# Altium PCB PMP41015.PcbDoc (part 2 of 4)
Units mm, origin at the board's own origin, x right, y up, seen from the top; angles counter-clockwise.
Board outline 173 x 85 mm, 2 copper layers (Top Layer, Bottom Layer), stack 1.575 mm thick; 89 components, 48 nets, 216 pads, 3458 vias.
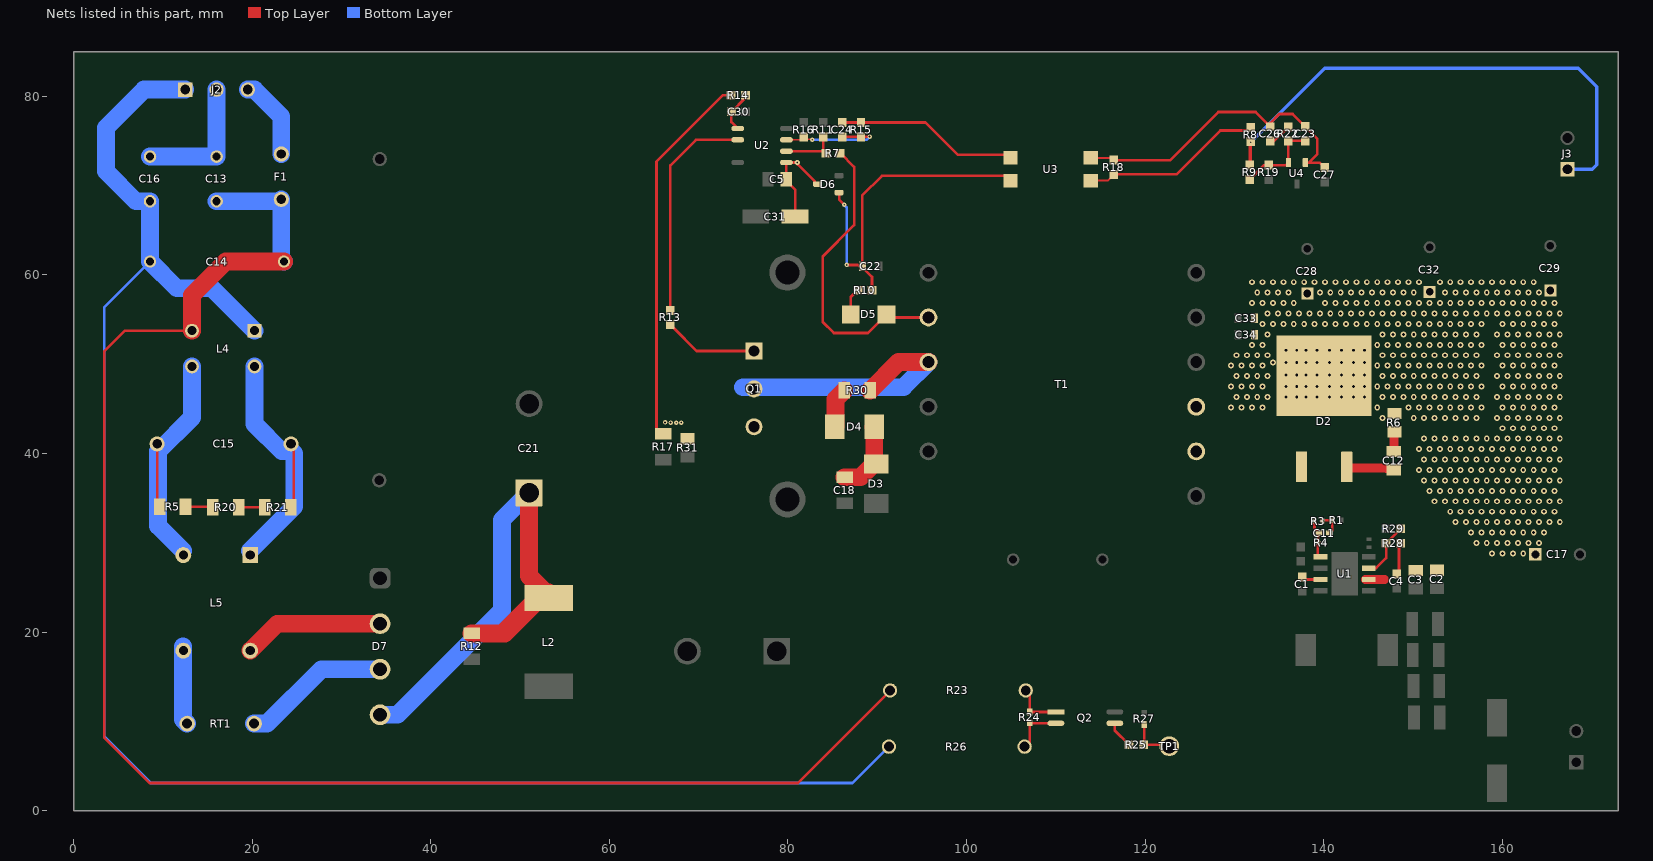
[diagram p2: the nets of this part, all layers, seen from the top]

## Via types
v1: diameter 0.4, hole 0.2, Top Layer to Bottom Layer, 2240 vias
v2: diameter 0.66, hole 0.33, Top Layer to Bottom Layer, 1066 vias
v3: diameter 0.5, hole 0.2, Top Layer to Bottom Layer, 105 vias
v4: diameter 0.67, hole 0.33, Top Layer to Bottom Layer, tented both sides, 41 vias
v5: diameter 0.5, hole 0.2, Top Layer to Bottom Layer, tented both sides, 4 vias
v6: diameter 0.61, hole 0.203, Top Layer to Bottom Layer, tented both sides, 2 vias

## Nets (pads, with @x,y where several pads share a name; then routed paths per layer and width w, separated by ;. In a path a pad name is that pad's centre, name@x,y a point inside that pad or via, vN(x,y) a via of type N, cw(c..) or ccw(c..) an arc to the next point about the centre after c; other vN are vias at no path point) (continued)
+24V: C2.1 C3.1 C4.1 C17.1 C28.1 C29.1 C32.1 C33.2 C34.2 D2.4 J3.1 R6.2 R8.2 R9.2 R28.2 U1.2 | length 63.7
  Top Layer w0.3: C4.1@148.178,26.505 148.438,26.764 148.438,29.759 R28.2@148.597,29.919
  Top Layer w0.4: R9.2@131.724,72.288 131.775,72.339 131.775,74.801 v6(131.826,74.851)
  Top Layer w1: U1.2@144.659,25.883 U1.2@145.048,25.883 146.841,25.883
  Bottom Layer w0.4: v6(131.826,74.851) 140.134,83.16 168.504,83.16 170.586,81.077 170.586,72.345 170.086,71.844 J3.1@167.307,71.844
  other v2: 158.852,28.804 160.02,28.804 161.188,28.804 162.357,28.804 157.099,29.972 158.267,29.972 159.436,29.972 160.604,29.972 161.773,29.972 162.941,29.972 164.109,29.972 156.515,31.14 157.683,31.14 158.852,31.14 160.02,31.14 161.188,31.14 162.357,31.14 163.525,31.14 164.694,31.14 154.762,32.309 155.931,32.309 157.099,32.309 158.267,32.309 159.436,32.309 160.604,32.309 161.773,32.309 162.941,32.309 164.109,32.309 165.278,32.309 166.446,32.309 154.178,33.477 155.346,33.477 156.515,33.477 157.683,33.477 158.852,33.477 160.02,33.477 161.188,33.477 162.357,33.477 163.525,33.477 164.694,33.477 165.862,33.477 152.425,34.646 153.594,34.646 154.762,34.646 155.931,34.646 157.099,34.646 158.267,34.646 159.436,34.646 160.604,34.646 161.773,34.646 162.941,34.646 164.109,34.646 165.278,34.646 166.446,34.646 151.841,35.814 153.01,35.814 154.178,35.814 155.346,35.814 156.515,35.814 157.683,35.814 158.852,35.814 160.02,35.814 161.188,35.814 162.357,35.814 163.525,35.814 164.694,35.814 165.862,35.814 151.257,36.982 152.425,36.982 153.594,36.982 154.762,36.982 155.931,36.982 157.099,36.982 158.267,36.982 159.436,36.982 160.604,36.982 161.773,36.982 162.941,36.982 164.109,36.982 165.278,36.982 166.446,36.982 150.673,38.151 151.841,38.151 153.01,38.151 154.178,38.151 155.346,38.151 156.515,38.151 157.683,38.151 158.852,38.151 160.02,38.151 161.188,38.151 162.357,38.151 163.525,38.151 164.694,38.151 165.862,38.151 151.257,39.319 152.425,39.319 153.594,39.319 154.762,39.319 155.931,39.319 157.099,39.319 158.267,39.319 159.436,39.319 160.604,39.319 161.773,39.319 162.941,39.319 164.109,39.319 165.278,39.319 166.446,39.319 150.673,40.488 151.841,40.488 153.01,40.488 154.178,40.488 155.346,40.488 156.515,40.488 157.683,40.488 158.852,40.488 160.02,40.488 161.188,40.488 162.357,40.488 163.525,40.488 164.694,40.488 165.862,40.488 151.257,41.656 152.425,41.656 153.594,41.656 154.762,41.656 155.931,41.656 157.099,41.656 158.267,41.656 159.436,41.656 160.604,41.656 161.773,41.656 162.941,41.656 164.109,41.656 165.278,41.656 166.446,41.656 160.02,42.824 161.188,42.824 162.357,42.824 163.525,42.824 164.694,42.824 165.862,42.824 146.583,43.993 150.089,43.993 151.257,43.993 152.425,43.993 153.594,43.993 154.762,43.993 155.931,43.993 157.099,43.993 159.436,43.993 160.604,43.993 161.773,43.993 162.941,43.993 164.109,43.993 165.278,43.993 166.446,43.993 129.642,45.161 130.81,45.161 131.978,45.161 133.147,45.161 145.999,45.161 149.504,45.161 150.673,45.161 151.841,45.161 153.01,45.161 154.178,45.161 155.346,45.161 156.515,45.161 157.683,45.161 160.02,45.161 161.188,45.161 162.357,45.161 163.525,45.161 164.694,45.161 165.862,45.161 130.226,46.33 131.394,46.33 132.563,46.33 133.731,46.33 146.583,46.33 147.752,46.33 148.92,46.33 150.089,46.33 151.257,46.33 152.425,46.33 153.594,46.33 154.762,46.33 155.931,46.33 157.099,46.33 159.436,46.33 160.604,46.33 161.773,46.33 162.941,46.33 164.109,46.33 165.278,46.33 166.446,46.33 129.642,47.498 130.81,47.498 131.978,47.498 133.147,47.498 145.999,47.498 147.168,47.498 148.336,47.498 149.504,47.498 150.673,47.498 151.841,47.498 153.01,47.498 154.178,47.498 155.346,47.498 156.515,47.498 157.683,47.498 160.02,47.498 161.188,47.498 162.357,47.498 163.525,47.498 164.694,47.498 165.862,47.498 130.226,48.666 131.394,48.666 132.563,48.666 133.731,48.666 146.583,48.666 147.752,48.666 148.92,48.666 150.089,48.666 151.257,48.666 152.425,48.666 153.594,48.666 154.762,48.666 155.931,48.666 157.099,48.666 159.436,48.666 160.604,48.666 161.773,48.666 162.941,48.666 164.109,48.666 165.278,48.666 166.446,48.666 129.642,49.835 130.81,49.835 131.978,49.835 133.147,49.835 145.999,49.835 147.168,49.835 148.336,49.835 149.504,49.835 150.673,49.835 151.841,49.835 153.01,49.835 154.178,49.835 155.346,49.835 156.515,49.835 157.683,49.835 160.02,49.835 161.188,49.835 162.357,49.835 163.525,49.835 164.694,49.835 165.862,49.835 130.226,51.003 131.394,51.003 132.563,51.003 133.731,51.003 146.583,51.003 147.752,51.003 148.92,51.003 150.089,51.003 151.257,51.003 152.425,51.003 153.594,51.003 154.762,51.003 155.931,51.003 157.099,51.003 159.436,51.003 160.604,51.003 161.773,51.003 162.941,51.003 164.109,51.003 165.278,51.003 166.446,51.003 131.978,52.172 133.147,52.172 145.999,52.172 147.168,52.172 148.336,52.172 149.504,52.172 150.673,52.172 151.841,52.172 153.01,52.172 154.178,52.172 155.346,52.172 156.515,52.172 157.683,52.172 160.02,52.172 161.188,52.172 162.357,52.172 163.525,52.172 164.694,52.172 165.862,52.172 133.731,53.34 146.583,53.34 147.752,53.34 148.92,53.34 150.089,53.34 151.257,53.34 152.425,53.34 153.594,53.34 154.762,53.34 155.931,53.34 157.099,53.34 159.436,53.34 160.604,53.34 161.773,53.34 162.941,53.34 164.109,53.34 165.278,53.34 166.446,53.34 133.147,54.508 134.315,54.508 135.484,54.508 136.652,54.508 137.82,54.508 138.989,54.508 140.157,54.508 141.326,54.508 142.494,54.508 143.662,54.508 144.831,54.508 145.999,54.508 147.168,54.508 148.336,54.508 149.504,54.508 150.673,54.508 151.841,54.508 153.01,54.508 154.178,54.508 155.346,54.508 156.515,54.508 157.683,54.508 160.02,54.508 161.188,54.508 162.357,54.508 163.525,54.508 164.694,54.508 165.862,54.508 133.731,55.677 134.899,55.677 136.068,55.677 137.236,55.677 138.405,55.677 139.573,55.677 140.741,55.677 141.91,55.677 143.078,55.677 144.247,55.677 145.415,55.677 146.583,55.677 147.752,55.677 148.92,55.677 150.089,55.677 151.257,55.677 152.425,55.677 153.594,55.677 154.762,55.677 155.931,55.677 157.099,55.677 158.267,55.677 159.436,55.677 160.604,55.677 161.773,55.677 162.941,55.677 164.109,55.677 165.278,55.677 166.446,55.677 131.978,56.845 133.147,56.845 134.315,56.845 135.484,56.845 136.652,56.845 140.157,56.845 141.326,56.845 142.494,56.845 143.662,56.845 144.831,56.845 145.999,56.845 147.168,56.845 148.336,56.845 149.504,56.845 150.673,56.845 151.841,56.845 153.01,56.845 154.178,56.845 155.346,56.845 156.515,56.845 157.683,56.845 158.852,56.845 160.02,56.845 161.188,56.845 162.357,56.845 163.525,56.845 164.694,56.845 165.862,56.845 132.563,58.014 133.731,58.014 134.899,58.014 136.068,58.014 139.573,58.014 140.741,58.014 141.91,58.014 143.078,58.014 144.247,58.014 145.415,58.014 146.583,58.014 147.752,58.014 148.92,58.014 150.089,58.014 153.594,58.014 154.762,58.014 155.931,58.014 157.099,58.014 158.267,58.014 159.436,58.014 160.604,58.014 161.773,58.014 162.941,58.014 164.109,58.014 131.978,59.182 133.147,59.182 134.315,59.182 135.484,59.182 136.652,59.182 137.82,59.182 138.989,59.182 140.157,59.182 141.326,59.182 142.494,59.182 143.662,59.182 144.831,59.182 145.999,59.182 147.168,59.182 148.336,59.182 149.504,59.182 150.673,59.182 153.01,59.182 154.178,59.182 155.346,59.182 156.515,59.182 157.683,59.182 158.852,59.182 160.02,59.182 161.188,59.182 162.357,59.182 163.525,59.182
  other v4: 135.765,46.33 136.983,46.33 138.023,46.33 139.239,46.33 140.649,46.33 142.008,46.33 143.359,46.33 144.571,46.33 135.768,47.498 136.987,47.498 138.027,47.498 139.242,47.498 140.652,47.498 142.011,47.498 143.362,47.498 144.574,47.498 135.768,48.767 136.987,48.767 138.027,48.767 139.242,48.767 140.652,48.767 142.011,48.767 143.362,48.767 144.574,48.767 134.315,50.189 135.765,50.189 136.983,50.189 138.023,50.189 139.239,50.189 140.649,50.189 142.008,50.189 143.359,50.189 144.571,50.189 135.765,51.561 136.983,51.561 138.023,51.561 139.239,51.561 140.649,51.561 142.008,51.561 143.359,51.561 144.571,51.561
BOOT: C1.1 U1.7 | length 2.1
  Top Layer w0.2: C1.1@137.623,26.177 C1.1@137.918,25.883
  Top Layer w0.3: C1.1@137.918,25.883 U1.7@139.648,25.883
Earth: C13.2 C16.1 J2.2 | length 15
  Bottom Layer w2: C16.1@8.55,73.25 C13.2@16,73.25 J2.2@16,80.75
FB: C11.2 R3.1 R4.2 U1.5 | length 4.4
  Top Layer w0.2: 139.325,28.745 U1.5@139.648,28.423 ; R4.2@139.325,29.919 R4.2@139.394,29.987
  Top Layer w0.3: R3.1@138.971,32.436 138.971,31.592 C11.2@139.473,31.09 139.394,31.011 R4.2@139.394,29.987 ; 139.325,28.745 R4.2@139.325,29.919
L: F1.2 J2.3 | length 9.2
  Bottom Layer w2: J2.3@19.5,80.75 20.24,80.75 23.25,77.74 F1.2@23.25,73.54
N: C14.2 C16.2 J2.1 L4.1 R26.1 | length 190.6
  Bottom Layer w0.3: C14.2@8.55,61.5 3.404,56.354 3.404,8.331 8.636,3.099 87.224,3.099 R26.1@91.298,7.173
  Bottom Layer w2: J2.1@12.5,80.75 7.877,80.75 3.607,76.479 3.607,71.603 6.959,68.25 C16.2@8.55,68.25 C14.2@8.55,61.5 11.55,58.5 15.5,58.5 L4.1@20.25,53.75
NetC5_1: C5.1 C31.1 D6.3 U2.1 | length 11.3
  Top Layer w0.3: U2.1@79.78,72.544 U2.1@79.825,72.59 ; C31.1@80.803,66.541 80.803,69.547 79.79,70.56 C5.1@79.79,70.726 79.825,70.761 U2.1@79.825,72.59 ; D6.3@83.318,70.162 83.118,70.162 82.968,70.312 82.968,70.512 81.106,72.375 81.106,72.531 v6(81.046,72.59) U2.1@79.825,72.59
NetC11_1: C11.1 R1.1 R3.2 | length 2.7
  Top Layer w0.3: R3.2@139.871,32.436 139.947,32.512 R1.1@140.953,32.512 140.953,31.369 C11.1@140.673,31.09
NetC12_1: C12.1 D2.1 D2.3 T1.8 T1.9 | length 5.5
  Top Layer w1: D2.3@142.586,38.493 142.586,38.388 146.967,38.388 147.028,38.327 147.717,38.327 C12.1@147.852,38.192
NetC12_2: C12.2 R6.1 | length 2.2
  Top Layer w1: C12.2@147.852,40.224 147.889,40.261 147.889,42.404 R6.1@147.926,42.44
NetC13_1: C13.1 C14.1 F1.1 L4.4 R23.1 | length 178.8
  Top Layer w0.3: L4.4@13.25,53.75 5.744,53.75 3.404,51.41 3.404,8.179 8.484,3.099 81.13,3.099 91.435,13.404 R23.1@91.435,13.462
  Top Layer w2: L4.4@13.25,53.75 13.25,57.725 17.025,61.5 C14.1@23.55,61.5
  Bottom Layer w2: C13.1@16,68.25 23.04,68.25 F1.1@23.25,68.46 23.25,61.8 C14.1@23.55,61.5
NetC15_1: C15.1 L4.3 L5.2 R5.2 | length 30.5
  Top Layer w0.3: C15.1@9.34,41.072 9.34,34.32 R5.2@9.624,34.036
  Bottom Layer w2: L5.2@12.25,29.1 9.458,31.892 9.458,40.25 13.25,44.042 L4.3@13.25,49.75
NetC15_2: C15.2 L4.2 L5.1 R21.1 | length 32.6
  Top Layer w0.3: C15.2@24.34,41.072 24.649,40.763 R21.1@24.649,33.871
  Bottom Layer w1: C15.2@24.458,40.25 24.7,40.008
  Bottom Layer w2: L5.1@19.75,29.1 24.7,34.05 24.7,40.008 ; L4.2@20.25,49.75 20.25,43.301 23.301,40.25 C15.2@24.458,40.25
NetC18_2: C18.2 D3.1 D4.1 | length 8.7
  Top Layer w2: C18.2@86.335,37.34 88.127,37.34 89.599,38.811 D3.1@89.742,38.811 ; D4.1@89.583,42.977 D4.1@89.662,42.897 ; D4.1@89.662,42.977 D4.1@89.662,42.897 ; D3.1@89.742,38.891 D3.1@89.821,38.811 ; D4.1@89.742,42.818 D4.1@89.662,42.897 ; D3.1@89.891,38.811 D3.1@89.821,38.811 ; D4.1@89.662,42.897 89.662,38.891 D3.1@89.742,38.811 ; D3.1@89.742,38.811 D3.1@89.821,38.811
NetC21_1: C21.1 D7.4 L2.1 R12.1 | length 62.5
  Top Layer w2: R12.1@44.571,19.847 48.021,19.847 ; C21.1@51.003,35.585 51.003,26.284 L2.1@52.861,24.426 ; 48.021,19.847 48.283,19.847 L2.1@52.611,24.176 ; 48.021,19.847 52.35,24.176 L2.1@52.611,24.176 ; L2.1@52.611,24.176 52.961,24.176 53.211,24.426 L2.1@52.861,24.426 ; L2.1@52.611,24.176 L2.1@52.861,24.426
  Bottom Layer w2: D7.4@34.32,10.733 36.27,10.733 38.091,12.554 47.955,22.418 47.955,32.537 C21.1@51.003,35.585
NetC22_2: C22.2 D6.1 R10.1 U3.4 | length 39.3
  Top Layer w0.3: D6.1@85.718,69.212 85.755,69.176 85.755,68.408 v3(86.296,67.867) ; v3(86.589,61.112) 87.824,61.112 88.155,60.782 C22.2@88.316,60.943 ; C22.2@88.365,60.96 88.332,60.96 C22.2@88.316,60.943 ; R10.1@89.421,58.268 89.421,59.779 88.316,60.884 C22.2@88.316,60.943 ; U3.4@104.923,70.561 104.39,71.095 90.526,71.095 88.316,68.885 C22.2@88.316,60.943
  Bottom Layer w0.3: v3(86.296,67.867) 86.296,67.813 86.589,67.521 v3(86.589,61.112)
NetC23_1: C23.1 R9.1 R19.2 R22.2 U4.2 | length 9.4
  Top Layer w0.3: R9.1@131.724,70.688 133.324,72.288 R19.2@133.833,72.288 135.768,72.288 U4.2@136.058,72.578 136.043,72.593 R22.2@136.043,74.99 136.068,75.015 C23.1@137.922,75.015
NetC23_2: C23.2 C26.2 C27.1 R18.1 U3.2 U4.1 | length 35.8
  Top Layer w0.2: U3.2@113.923,73.101 116.268,73.101 R18.1@116.51,72.86
  Top Layer w0.3: R18.1@116.51,72.86 122.822,72.86 128.207,78.245 132.382,78.245 C26.2@134.036,76.591 134.036,77.026 135.026,78.016 136.521,78.016 C23.2@137.922,76.615 139.294,75.244 139.294,73.52 138.351,72.578 ; U4.1@137.958,72.578 138.351,72.578 ; C27.1@140.106,72.009 139.537,72.578 138.351,72.578
NetC24_1: C24.1 R15.2 R16.2 U2.3 | length 13.2
  Top Layer w0.2: U2.3@79.825,75.13 81.674,75.13 R16.2@81.884,75.34 ; v3(82.715,75.131) 82.634,75.131 82.572,75.193 82.031,75.193 R16.2@81.884,75.34 ; R16.2@81.884,75.34 81.993,75.449 R16.2@81.775,75.449 R16.2@81.884,75.34
  Top Layer w0.3: C24.1@86.064,75.47 R15.2@88.181,75.47 88.198,75.487 v3(89.141,75.487)
  Bottom Layer w0.3: v3(82.715,75.131) 88.786,75.131 v3(89.141,75.487)
NetC24_2: C24.2 R15.1 U3.3 | length 20.5
  Top Layer w0.3: C24.2@86.064,77.07 95.408,77.07 99.013,73.465 104.559,73.465 U3.3@104.923,73.101
NetC26_1: C26.1 R22.1 | length 2.7
  Top Layer w0.3: C26.1@134.036,74.991 134.444,74.991 R22.1@136.043,76.59
NetC30_1: C30.1 R14.1 U2.5 | length 4.8
  Top Layer w0.2: C30.1@73.664,78.27 C30.1@73.664,78.42
  Top Layer w0.3: U2.5@74.375,76.4 73.664,77.112 C30.1@73.664,78.27 75.235,79.841 R14.1@75.235,80.11
NetD4_2: D4.2 R30.2 | length 4.5
  Top Layer w2: D4.2@85.242,42.977 85.322,43.056 85.322,46.081 R30.2@86.307,47.066
NetD5_1: D5.1 R10.2 | length 3
  Top Layer w0.3: D5.1@87.027,55.575 87.027,57.499 87.796,58.268 R10.2@87.821,58.268
NetD5_2: D5.2 R7.2 T1.2 | length 34.4
  Top Layer w0.3: R7.2@85.839,73.64 85.864,73.64 87.414,72.09 87.414,65.57 83.879,62.035 83.879,54.754 85.141,53.492 88.944,53.492 D5.2@91.027,55.575 91.369,55.234 T1.2@95.733,55.234
NetD7_2: D7.2 L5.4 | length 15.8
  Top Layer w2: L5.4@19.777,17.916 22.794,20.933 D7.2@34.32,20.933
NetD7_3: D7.3 RT1.2 | length 16.6
  Bottom Layer w2: RT1.2@20.202,9.75 21.663,9.75 27.746,15.833 D7.3@34.32,15.833
NetL5_3: L5.3 RT1.1 | length 8.9
  Bottom Layer w2: L5.3@12.25,18.4 L5.3@12.25,17.916 ; L5.3@12.277,17.916 L5.3@12.25,17.916 ; RT1.1@12.702,9.75 12.25,10.202 L5.3@12.25,17.916
NetQ1_1: Q1.1 R13.2 | length 11.1
  Top Layer w0.3: R13.2@67.142,54.119 R13.2@66.827,54.434 66.827,54.409 67.152,54.084 67.177,54.084 69.775,51.486 Q1.1@76.198,51.486
NetQ1_2: Q1.2 R30.1 T1.3 | length 29.8
  Top Layer w2: R30.1@89.207,47.066 92.374,50.234 T1.3@95.733,50.234
  Bottom Layer w2: 74.967,47.422 92.921,47.422 T1.3@95.733,50.234
NetQ1_3: Q1.3 R14.2 R17.2 R31.2 | length 42.4
  Top Layer w0.3: R17.2@66.048,42.217 65.773,42.217 65.273,42.717 65.273,72.698 72.685,80.11 R14.2@73.635,80.11
  other v3: 67.488,43.434 66.853,43.459 68.047,43.459 66.243,43.485
NetQ2_1: Q2.1 R23.2 R24.2 | length 5.5
  Top Layer w0.3: R23.2@106.635,13.462 107.088,13.008 R24.2@107.088,11.053 Q2.1@110.003,11.053
NetQ2_2: Q2.2 R24.1 R26.2 | length 5.9
  Top Layer w0.2: R24.1@107.053,9.818 R24.1@107.088,9.818 ; Q2.2@109.968,9.818 Q2.2@110.003,9.783
  Top Layer w0.3: R26.2@106.508,7.163 107.088,7.743 R24.1@107.088,9.818 ; R24.1@107.088,9.853 R24.1@107.088,9.818 ; Q2.2@110.003,9.783 107.123,9.783 R24.1@107.088,9.818
NetQ2_3: Q2.3 R25.1 | length 3.1
  Top Layer w0.3: Q2.3@116.603,9.783 116.603,8.987 R25.1@118.199,7.391
NetR5_1: R5.1 R20.2 | length 3.1
  Top Layer w0.3: R5.1@12.524,34.036 R20.2@15.517,34.036
  Top Layer w1: R20.2@15.517,34.036 R20.2@15.568,33.985
NetR7_1: R7.1 R11.2 U2.2 | length 6.1
  Top Layer w0.3: U2.2@79.825,73.86 R7.1@84.019,73.86 ; R11.2@83.964,75.47 83.964,73.915 R7.1@84.019,73.86 ; R7.1@84.239,73.64 R7.1@84.019,73.86
NetR8_1: R8.1 R18.2 U3.1 | length 20.4
  Top Layer w0.2: U3.1@113.923,70.561 115.811,70.561 R18.2@116.51,71.26
  Top Layer w0.3: R18.2@116.51,71.26 123.508,71.26 128.424,76.176 131.501,76.176 131.826,76.501 R8.1@131.826,76.526
NetR13_1: R13.1 U2.6 | length 25
  Top Layer w0.3: R13.1@66.827,56.034 66.827,72.254 69.704,75.13 U2.6@74.375,75.13
NetR20_1: R20.1 R21.2 | length 3
  Top Layer w0.3: R20.1@18.468,33.985 21.385,33.985 R21.2@21.41,33.96
NetR25_2: R25.2 R27.2 TP1.1 | length 5.3
  Top Layer w0.3: R27.2@119.893,9.662 119.893,7.486 R25.2@119.799,7.391 122.532,7.391 TP1.1@122.707,7.216
NetR28_1: R28.1 R29.2 U1.3 | length 6.4
  Top Layer w0.3: U1.3@145.048,27.153 145.872,27.153 146.997,28.278 R28.1@146.997,29.919 148.603,31.524 R29.2@148.603,31.595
